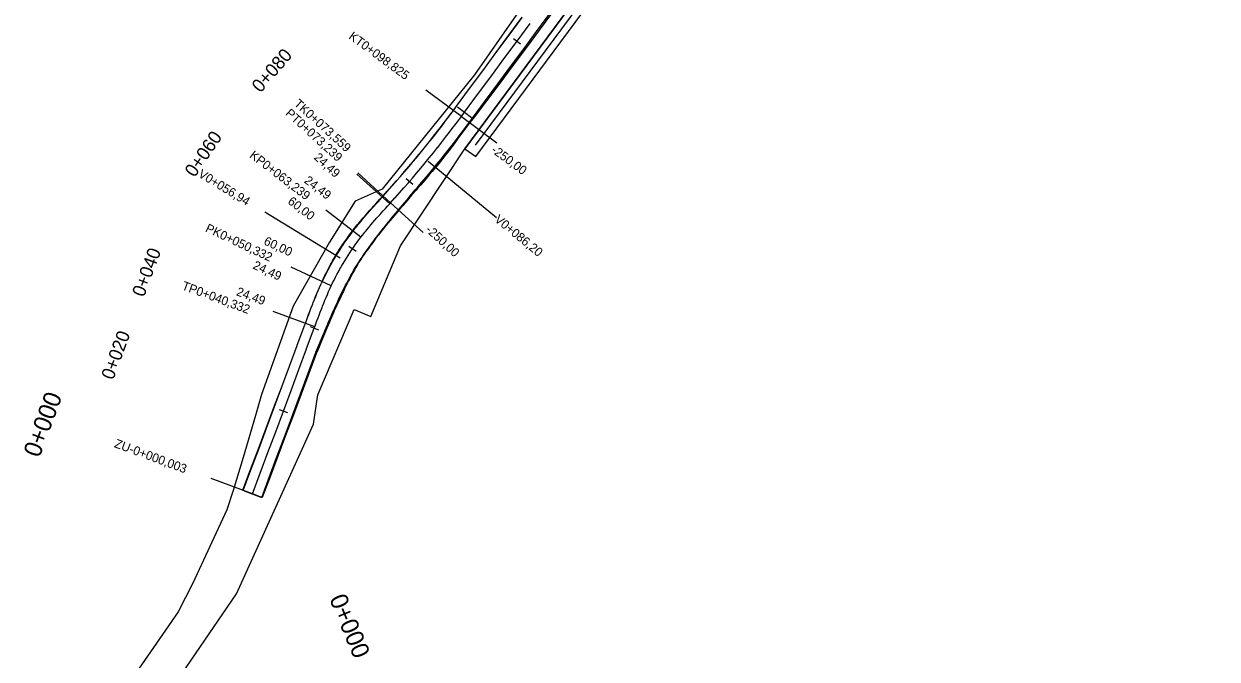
# Model space of a CAD drawing. Extents: x -636600 to -628587, y -1090963 to -1085869.
# Drawn here: x -635180 to -634910.1, y -1088982.7 to -1088839 of the extents above; entities that cross this region are included whole.
import ezdxf

# ---------------------------------------------------------------- set-up
doc = ezdxf.new("R2010")
doc.units = 0
for name, color, linetype in [('01_PARCELY_NÁVRH_PC', 7, 'Continuous'), ('06_ÚSES_IP_NAVRH', 7, 'Continuous'), ('HEKTOMETRY100', 7, 'Continuous'), ('HEKTOMETRY20', 7, 'Continuous'), ('HL_BODY', 7, 'Continuous'), ('POLOMERY', 7, 'Continuous'), ('situace_osa', 7, 'Continuous'), ('situace_těleso', 7, 'Continuous'), ('situace_vozovka', 7, 'Continuous'), ('VRCHOLY', 7, 'Continuous')]:
    doc.layers.add(name, color=color, linetype=linetype)

msp = doc.modelspace()

# ---------------------------------------------------------------- linework, layer by layer
at = {"layer": '01_PARCELY_NÁVRH_PC'}
for points in [[(-634861.29, -1088662.55), (-634916.65, -1088673.39), (-634939.28, -1088680.12), (-634951.36, -1088684.51), (-634967.33, -1088691.91), (-634983.87, -1088704.68), (-634995.51, -1088719.97), (-635021.98, -1088768.35), (-635040.92, -1088797.21), (-635078.05, -1088850.49), (-635098.99, -1088876.35), (-635105.07, -1088879.12), (-635110.88, -1088888.39), (-635119.1, -1088902.88), (-635126.27, -1088922.85), (-635127.59, -1088927.58), (-635130.38, -1088937.08), (-635132.64, -1088944.55), (-635134.08, -1088948.9), (-635141.78, -1088965.52), (-635145.13, -1088972.03), (-635147.95, -1088976.12), (-635154.73, -1088985.94)], [(-635153.56, -1088999.63), (-635131.9, -1088967.9), (-635114.47, -1088929.52), (-635113.55, -1088922.94), (-635105.31, -1088903.63), (-635101.54, -1088905.22), (-635094.81, -1088889.19), (-635080.24, -1088867.26), (-635022.41, -1088789.13), (-635007.04, -1088763.27), (-634984.89, -1088721.83), (-634957.8, -1088700.36), (-634947.7, -1088694.08), (-634936.69, -1088689.67), (-634913.24, -1088683.86), (-634889.39, -1088680.18)]]:
    msp.add_lwpolyline(points, dxfattribs=at)
msp.add_lwpolyline([(-635080.24, -1088867.26), (-635077.78, -1088868.98), (-635019.9, -1088790.79), (-635004.42, -1088764.74), (-634978.99, -1088717.15), (-634984.89, -1088721.83), (-635007.04, -1088763.27), (-635022.41, -1088789.13)], close=True, dxfattribs=at)
at = {"layer": '06_ÚSES_IP_NAVRH'}
msp.add_lwpolyline([(-635077.87, -1088866.44), (-635021.22, -1088790.03), (-635005.04, -1088762.52), (-634983.55, -1088723.1)], dxfattribs=at)
at = {"layer": 'HEKTOMETRY100'}
for points in [[(-635081.94, -1088857.77), (-635078.72, -1088860.15)], [(-635130.14, -1088944.63), (-635126.4, -1088946.03)], [(-635130.14, -1088944.63), (-635126.39, -1088946.02)]]:
    msp.add_lwpolyline(points, dxfattribs=at)
at = {"layer": 'HEKTOMETRY20'}
for points in [[(-635069.24, -1088842.28), (-635067.64, -1088843.47)], [(-635093.53, -1088873.95), (-635092.02, -1088875.26)], [(-635106.5, -1088889.3), (-635104.85, -1088890.43)], [(-635115.27, -1088907.48), (-635113.4, -1088908.18)], [(-635122.24, -1088926.23), (-635120.36, -1088926.93)], [(-635129.21, -1088944.98), (-635127.33, -1088945.68)]]:
    msp.add_lwpolyline(points, dxfattribs=at)
at = {"layer": 'HL_BODY'}
for points in [[(-635081.03, -1088859.9), (-635089.07, -1088853.96)], [(-635097.26, -1088879.67), (-635104.66, -1088872.94)], [(-635097.05, -1088879.43), (-635104.45, -1088872.7)], [(-635103.78, -1088887.25), (-635111.71, -1088881.16)], [(-635110.48, -1088898.25), (-635119.53, -1088894)], [(-635114.22, -1088907.52), (-635123.59, -1088904.04)], [(-635128.27, -1088945.33), (-635137.64, -1088941.85)]]:
    msp.add_lwpolyline(points, dxfattribs=at)
at = {"layer": 'POLOMERY'}
for points in [[(-635081.03, -1088859.9), (-635072.99, -1088865.85)], [(-635097.26, -1088879.67), (-635104.66, -1088872.94)], [(-635103.78, -1088887.25), (-635111.71, -1088881.16)], [(-635097.05, -1088879.43), (-635089.65, -1088886.15)], [(-635110.48, -1088898.25), (-635119.53, -1088894)], [(-635114.22, -1088907.52), (-635123.59, -1088904.04)], [(-635128.27, -1088945.33), (-635137.64, -1088941.85)]]:
    msp.add_lwpolyline(points, dxfattribs=at)
at = {"layer": 'situace_osa'}
msp.add_lwpolyline([(-635128.27, -1088945.33), (-635126.53, -1088940.64), (-635124.79, -1088935.95), (-635123.04, -1088931.27), (-635121.3, -1088926.58), (-635119.56, -1088921.89), (-635117.82, -1088917.21), (-635116.08, -1088912.52), (-635116.05, -1088912.46), (-635114.33, -1088907.83), (-635114.22, -1088907.52), (-635113.97, -1088906.85), (-635113.72, -1088906.18), (-635113.47, -1088905.51), (-635113.22, -1088904.85), (-635112.96, -1088904.18), (-635112.7, -1088903.51), (-635112.56, -1088903.16), (-635112.44, -1088902.85), (-635112.18, -1088902.18), (-635111.91, -1088901.52), (-635111.63, -1088900.86), (-635111.35, -1088900.21), (-635111.07, -1088899.55), (-635110.78, -1088898.9), (-635110.62, -1088898.55), (-635110.59, -1088898.49), (-635110.48, -1088898.25), (-635110.17, -1088897.6), (-635109.85, -1088896.96), (-635109.53, -1088896.32), (-635109.19, -1088895.69), (-635108.85, -1088895.05), (-635108.51, -1088894.43), (-635108.33, -1088894.11), (-635108.15, -1088893.8), (-635107.79, -1088893.18), (-635107.42, -1088892.57), (-635107.05, -1088891.96), (-635106.66, -1088891.35), (-635106.27, -1088890.75), (-635105.87, -1088890.16), (-635105.68, -1088889.87), (-635105.47, -1088889.56), (-635105.06, -1088888.98), (-635104.64, -1088888.4), (-635104.21, -1088887.82), (-635103.78, -1088887.25), (-635103.75, -1088887.21), (-635103.34, -1088886.68), (-635102.9, -1088886.12), (-635102.69, -1088885.87), (-635102.45, -1088885.57), (-635101.99, -1088885.02), (-635101.53, -1088884.47), (-635101.07, -1088883.93), (-635100.6, -1088883.39), (-635100.13, -1088882.85), (-635099.66, -1088882.32), (-635099.43, -1088882.07), (-635099.18, -1088881.78), (-635098.7, -1088881.25), (-635098.22, -1088880.72), (-635097.74, -1088880.19), (-635097.26, -1088879.67), (-635097.05, -1088879.43), (-635096.08, -1088878.36), (-635096.05, -1088878.33), (-635095.06, -1088877.22), (-635094.08, -1088876.1), (-635093.91, -1088875.91), (-635093.1, -1088874.98), (-635092.78, -1088874.61), (-635092.13, -1088873.86), (-635091.17, -1088872.72), (-635090.21, -1088871.59), (-635089.55, -1088870.79), (-635089.26, -1088870.44), (-635088.32, -1088869.29), (-635087.38, -1088868.14), (-635086.46, -1088866.98), (-635086.4, -1088866.91), (-635085.53, -1088865.81), (-635084.62, -1088864.64), (-635083.71, -1088863.47), (-635083.33, -1088862.96), (-635082.81, -1088862.28), (-635081.92, -1088861.1), (-635081.03, -1088859.9), (-635080.33, -1088858.96), (-635077.36, -1088854.94), (-635074.38, -1088850.92), (-635071.41, -1088846.9), (-635068.44, -1088842.88), (-635065.47, -1088838.86)], dxfattribs=at)
at = {"layer": 'situace_těleso'}
msp.add_lwpolyline([(-635060.45, -1088836.34), (-635063.41, -1088840.38), (-635066.38, -1088844.4), (-635069.37, -1088848.4), (-635072.37, -1088852.41), (-635075.36, -1088856.42), (-635078.39, -1088860.39), (-635079.11, -1088861.32), (-635080.01, -1088862.52), (-635080.91, -1088863.72), (-635081.43, -1088864.41), (-635081.82, -1088864.92), (-635082.71, -1088866.13), (-635083.61, -1088867.32), (-635084.47, -1088868.44), (-635084.53, -1088868.51), (-635085.45, -1088869.7), (-635086.4, -1088870.86), (-635087.36, -1088872.02), (-635087.65, -1088872.36), (-635088.33, -1088873.16), (-635089.31, -1088874.3), (-635090.29, -1088875.43), (-635090.95, -1088876.19), (-635091.28, -1088876.56), (-635092.1, -1088877.49), (-635092.27, -1088877.69), (-635093.23, -1088878.85), (-635094.19, -1088879.99), (-635094.22, -1088880.03), (-635095.17, -1088881.14), (-635095.37, -1088881.38), (-635095.84, -1088881.93), (-635096.3, -1088882.47), (-635096.76, -1088883.01), (-635097.21, -1088883.55), (-635097.45, -1088883.84), (-635097.66, -1088884.09), (-635098.11, -1088884.63), (-635098.56, -1088885.17), (-635099, -1088885.71), (-635099.43, -1088886.25), (-635099.86, -1088886.79), (-635100.29, -1088887.34), (-635100.5, -1088887.63), (-635100.69, -1088887.89), (-635101.09, -1088888.45), (-635101.46, -1088888.96), (-635101.49, -1088889), (-635101.9, -1088889.55), (-635102.3, -1088890.1), (-635102.7, -1088890.65), (-635103.09, -1088891.21), (-635103.29, -1088891.5), (-635103.48, -1088891.78), (-635103.86, -1088892.34), (-635104.22, -1088892.92), (-635104.57, -1088893.51), (-635104.91, -1088894.1), (-635105.25, -1088894.69), (-635105.58, -1088895.29), (-635105.74, -1088895.58), (-635105.9, -1088895.89), (-635106.22, -1088896.49), (-635106.54, -1088897.09), (-635106.85, -1088897.7), (-635107.16, -1088898.31), (-635107.45, -1088898.92), (-635107.74, -1088899.53), (-635107.85, -1088899.76), (-635107.88, -1088899.82), (-635108.04, -1088900.15), (-635108.34, -1088900.76), (-635108.64, -1088901.38), (-635108.94, -1088902), (-635109.22, -1088902.63), (-635109.51, -1088903.26), (-635109.79, -1088903.9), (-635109.92, -1088904.19), (-635110.07, -1088904.54), (-635110.35, -1088905.18), (-635110.62, -1088905.83), (-635110.89, -1088906.48), (-635111.17, -1088907.14), (-635111.44, -1088907.79), (-635111.72, -1088908.45), (-635111.85, -1088908.76), (-635113.77, -1088913.31), (-635113.79, -1088913.37), (-635115.54, -1088918.05), (-635117.27, -1088922.74), (-635119.02, -1088927.43), (-635120.79, -1088932.1), (-635122.55, -1088936.78), (-635124.31, -1088941.46), (-635126.08, -1088946.14), (-635126.16, -1088946.11), (-635128.27, -1088945.33), (-635130.38, -1088944.54), (-635130.48, -1088944.5), (-635128.73, -1088939.82), (-635126.97, -1088935.14), (-635125.2, -1088930.46), (-635123.44, -1088925.79), (-635121.67, -1088921.11), (-635119.95, -1088916.41), (-635118.19, -1088911.73), (-635118.17, -1088911.67), (-635116.45, -1088907.05), (-635116.34, -1088906.73), (-635116.09, -1088906.06), (-635115.84, -1088905.39), (-635115.59, -1088904.72), (-635115.33, -1088904.04), (-635115.08, -1088903.37), (-635114.82, -1088902.69), (-635114.68, -1088902.33), (-635114.55, -1088902.01), (-635114.28, -1088901.34), (-635114.01, -1088900.66), (-635113.73, -1088899.98), (-635113.44, -1088899.31), (-635113.14, -1088898.63), (-635112.83, -1088897.96), (-635112.66, -1088897.61), (-635112.63, -1088897.54), (-635112.52, -1088897.29), (-635112.22, -1088896.61), (-635111.9, -1088895.94), (-635111.58, -1088895.27), (-635111.24, -1088894.6), (-635110.9, -1088893.94), (-635110.56, -1088893.28), (-635110.38, -1088892.94), (-635110.2, -1088892.62), (-635109.84, -1088891.97), (-635109.46, -1088891.33), (-635109.08, -1088890.69), (-635108.67, -1088890.06), (-635108.26, -1088889.44), (-635107.84, -1088888.82), (-635107.64, -1088888.53), (-635107.42, -1088888.21), (-635106.99, -1088887.6), (-635106.55, -1088887), (-635106.1, -1088886.4), (-635105.65, -1088885.81), (-635105.62, -1088885.77), (-635105.19, -1088885.23), (-635104.73, -1088884.65), (-635104.51, -1088884.39), (-635104.26, -1088884.08), (-635103.79, -1088883.52), (-635103.31, -1088882.96), (-635102.84, -1088882.4), (-635102.37, -1088881.85), (-635101.88, -1088881.3), (-635101.4, -1088880.76), (-635101.18, -1088880.51), (-635100.92, -1088880.23), (-635100.43, -1088879.69), (-635099.95, -1088879.16), (-635099.46, -1088878.63), (-635098.98, -1088878.11), (-635098.76, -1088877.87), (-635097.8, -1088876.81), (-635097.77, -1088876.78), (-635096.79, -1088875.68), (-635095.81, -1088874.58), (-635095.65, -1088874.4), (-635094.84, -1088873.48), (-635094.52, -1088873.1), (-635093.88, -1088872.36), (-635092.92, -1088871.24), (-635091.97, -1088870.12), (-635091.31, -1088869.33), (-635091.03, -1088868.99), (-635090.09, -1088867.85), (-635089.16, -1088866.71), (-635088.24, -1088865.56), (-635088.18, -1088865.49), (-635087.32, -1088864.41), (-635086.41, -1088863.25), (-635085.51, -1088862.08), (-635085.13, -1088861.59), (-635084.62, -1088860.92), (-635083.73, -1088859.74), (-635082.85, -1088858.56), (-635082.15, -1088857.62), (-635079.17, -1088853.6), (-635076.2, -1088849.58), (-635073.23, -1088845.55), (-635070.27, -1088841.53), (-635067.32, -1088837.49)], dxfattribs=at)
at = {"layer": 'situace_vozovka'}
for points in [[(-635130.38, -1088944.54), (-635128.64, -1088939.86), (-635126.89, -1088935.17), (-635125.15, -1088930.48), (-635123.41, -1088925.8), (-635121.67, -1088921.11), (-635119.93, -1088916.42), (-635118.18, -1088911.74), (-635118.16, -1088911.67), (-635116.44, -1088907.05), (-635116.33, -1088906.74), (-635116.08, -1088906.07), (-635115.83, -1088905.4), (-635115.57, -1088904.72), (-635115.32, -1088904.05), (-635115.06, -1088903.37), (-635114.8, -1088902.7), (-635114.66, -1088902.33), (-635114.54, -1088902.02), (-635114.26, -1088901.34), (-635113.99, -1088900.67), (-635113.71, -1088899.99), (-635113.42, -1088899.31), (-635113.13, -1088898.64), (-635112.82, -1088897.97), (-635112.66, -1088897.61), (-635112.63, -1088897.54), (-635112.51, -1088897.29), (-635112.19, -1088896.62), (-635111.86, -1088895.96), (-635111.53, -1088895.29), (-635111.18, -1088894.63), (-635110.83, -1088893.98), (-635110.47, -1088893.33), (-635110.28, -1088893), (-635110.1, -1088892.68), (-635109.73, -1088892.04), (-635109.34, -1088891.4), (-635108.95, -1088890.77), (-635108.56, -1088890.14), (-635108.15, -1088889.51), (-635107.74, -1088888.9), (-635107.54, -1088888.6), (-635107.32, -1088888.28), (-635106.89, -1088887.67), (-635106.45, -1088887.07), (-635106.01, -1088886.47), (-635105.56, -1088885.88), (-635105.53, -1088885.84), (-635105.11, -1088885.29), (-635104.65, -1088884.72), (-635104.44, -1088884.45), (-635104.19, -1088884.14), (-635103.72, -1088883.58), (-635103.25, -1088883.02), (-635102.77, -1088882.46), (-635102.3, -1088881.91), (-635101.82, -1088881.36), (-635101.34, -1088880.82), (-635101.11, -1088880.57), (-635100.85, -1088880.28), (-635100.37, -1088879.75), (-635099.89, -1088879.21), (-635099.41, -1088878.68), (-635098.93, -1088878.15), (-635098.71, -1088877.92), (-635097.76, -1088876.86), (-635097.73, -1088876.82), (-635096.74, -1088875.72), (-635095.77, -1088874.62), (-635095.61, -1088874.43), (-635094.8, -1088873.51), (-635094.48, -1088873.14), (-635093.84, -1088872.39), (-635092.89, -1088871.27), (-635091.94, -1088870.14), (-635091.28, -1088869.35), (-635091, -1088869.01), (-635090.06, -1088867.87), (-635089.14, -1088866.73), (-635088.22, -1088865.58), (-635088.16, -1088865.51), (-635087.3, -1088864.42), (-635086.4, -1088863.26), (-635085.5, -1088862.1), (-635085.11, -1088861.6), (-635084.6, -1088860.93), (-635083.72, -1088859.75), (-635082.84, -1088858.57), (-635082.14, -1088857.62), (-635079.17, -1088853.6), (-635076.19, -1088849.58), (-635073.22, -1088845.56), (-635070.25, -1088841.54), (-635067.28, -1088837.52)], [(-635126.16, -1088946.11), (-635124.42, -1088941.42), (-635122.68, -1088936.74), (-635120.93, -1088932.05), (-635119.19, -1088927.36), (-635117.45, -1088922.68), (-635115.71, -1088917.99), (-635113.97, -1088913.3), (-635113.94, -1088913.24), (-635112.04, -1088908.69), (-635111.91, -1088908.38), (-635111.64, -1088907.72), (-635111.36, -1088907.06), (-635111.08, -1088906.41), (-635110.81, -1088905.76), (-635110.53, -1088905.11), (-635110.25, -1088904.47), (-635110.1, -1088904.12), (-635109.97, -1088903.83), (-635109.68, -1088903.19), (-635109.4, -1088902.56), (-635109.1, -1088901.93), (-635108.81, -1088901.3), (-635108.51, -1088900.69), (-635108.2, -1088900.07), (-635108.03, -1088899.75), (-635108, -1088899.69), (-635107.9, -1088899.46), (-635107.6, -1088898.85), (-635107.3, -1088898.23), (-635106.99, -1088897.62), (-635106.68, -1088897.02), (-635106.35, -1088896.42), (-635106.02, -1088895.82), (-635105.85, -1088895.52), (-635105.68, -1088895.23), (-635105.34, -1088894.64), (-635104.99, -1088894.05), (-635104.63, -1088893.47), (-635104.26, -1088892.89), (-635103.89, -1088892.32), (-635103.51, -1088891.75), (-635103.33, -1088891.48), (-635103.13, -1088891.19), (-635102.73, -1088890.63), (-635102.33, -1088890.08), (-635101.93, -1088889.53), (-635101.52, -1088888.98), (-635101.49, -1088888.94), (-635101.12, -1088888.43), (-635100.72, -1088887.87), (-635100.53, -1088887.62), (-635100.31, -1088887.32), (-635099.89, -1088886.77), (-635099.46, -1088886.22), (-635099.04, -1088885.68), (-635098.6, -1088885.13), (-635098.16, -1088884.59), (-635097.72, -1088884.04), (-635097.51, -1088883.79), (-635097.27, -1088883.5), (-635096.82, -1088882.95), (-635096.36, -1088882.41), (-635095.91, -1088881.86), (-635095.45, -1088881.31), (-635095.24, -1088881.07), (-635094.31, -1088879.95), (-635094.28, -1088879.92), (-635093.33, -1088878.76), (-635092.38, -1088877.59), (-635092.22, -1088877.39), (-635091.4, -1088876.46), (-635091.07, -1088876.08), (-635090.42, -1088875.32), (-635089.45, -1088874.18), (-635088.49, -1088873.03), (-635087.82, -1088872.22), (-635087.53, -1088871.88), (-635086.58, -1088870.72), (-635085.63, -1088869.55), (-635084.7, -1088868.38), (-635084.64, -1088868.31), (-635083.76, -1088867.2), (-635082.84, -1088866.02), (-635081.93, -1088864.84), (-635081.54, -1088864.33), (-635081.02, -1088863.64), (-635080.11, -1088862.45), (-635079.22, -1088861.24), (-635078.52, -1088860.3), (-635075.55, -1088856.28), (-635072.58, -1088852.26), (-635069.6, -1088848.23), (-635066.63, -1088844.21), (-635063.66, -1088840.19), (-635060.69, -1088836.17)]]:
    msp.add_lwpolyline(points, dxfattribs=at)
at = {"layer": 'VRCHOLY'}
for points in [[(-635088.54, -1088870.07), (-635073.08, -1088882.76)], [(-635108.43, -1088891.96), (-635125.52, -1088881.56)]]:
    msp.add_lwpolyline(points, dxfattribs=at)

# ---------------------------------------------------------------- texts
at = {"layer": 'HEKTOMETRY100'}
for rotation, p in [(69.6103, (-635176.49, -1088937.3)), (69.6103, (-635176.49, -1088937.3)), (292.4277, (-635110.99, -1088969.01))]:
    msp.add_text('0+000', height=4, rotation=rotation, dxfattribs=at).set_placement(p)
at = {"layer": 'HEKTOMETRY20'}
for s, rotation, p in [('0+080', 49.2122, (-635126.47, -1088854.72)), ('0+060', 55.6039, (-635141.38, -1088873.86)), ('0+040', 69.6103, (-635152.84, -1088900.94)), ('0+020', 69.6103, (-635159.81, -1088919.69))]:
    msp.add_text(s, height=3, rotation=rotation, dxfattribs=at).set_placement(p)
at = {"layer": 'HL_BODY'}
for s, rotation, p in [('KT0+098,825', 323.5265, (-635106.7, -1088842.17)), ('TK0+073,559', 317.736, (-635119.07, -1088857.28)), ('PT0+073,239', 317.736, (-635121.01, -1088859.44)), ('KP0+063,239', 322.5107, (-635129.13, -1088869.06)), ('PK0+050,332', 334.8357, (-635139.12, -1088885.9)), ('TP0+040,332', 339.6103, (-635144.44, -1088899.01)), ('ZU-0+000,003', 339.6103, (-635159.7, -1088934.71))]:
    msp.add_text(s, height=2, rotation=rotation, dxfattribs=at).set_placement(p)
at = {"layer": 'POLOMERY'}
for s, rotation, p in [('24,49', 317.736, (-635114.54, -1088869.41)), ('-250,00', 323.5265, (-635074.47, -1088867.86)), ('24,49', 322.5107, (-635116.77, -1088874.76)), ('60,00', 322.5107, (-635120.49, -1088879.47)), ('60,00', 334.8357, (-635125.92, -1088888.79)), ('-250,00', 317.736, (-635089.31, -1088885.78)), ('24,49', 334.8357, (-635128.38, -1088894.26)), ('24,49', 339.6103, (-635132.11, -1088900.34))]:
    msp.add_text(s, height=2, rotation=rotation, dxfattribs=at).set_placement(p)
at = {"layer": 'VRCHOLY'}
for s, rotation, p in [('V0+056,94', 328.6732, (-635140.74, -1088873.46)), ('V0+086,20', 320.6313, (-635073.72, -1088883.53))]:
    msp.add_text(s, height=2, rotation=rotation, dxfattribs=at).set_placement(p)

doc.saveas('drawing.dxf')
